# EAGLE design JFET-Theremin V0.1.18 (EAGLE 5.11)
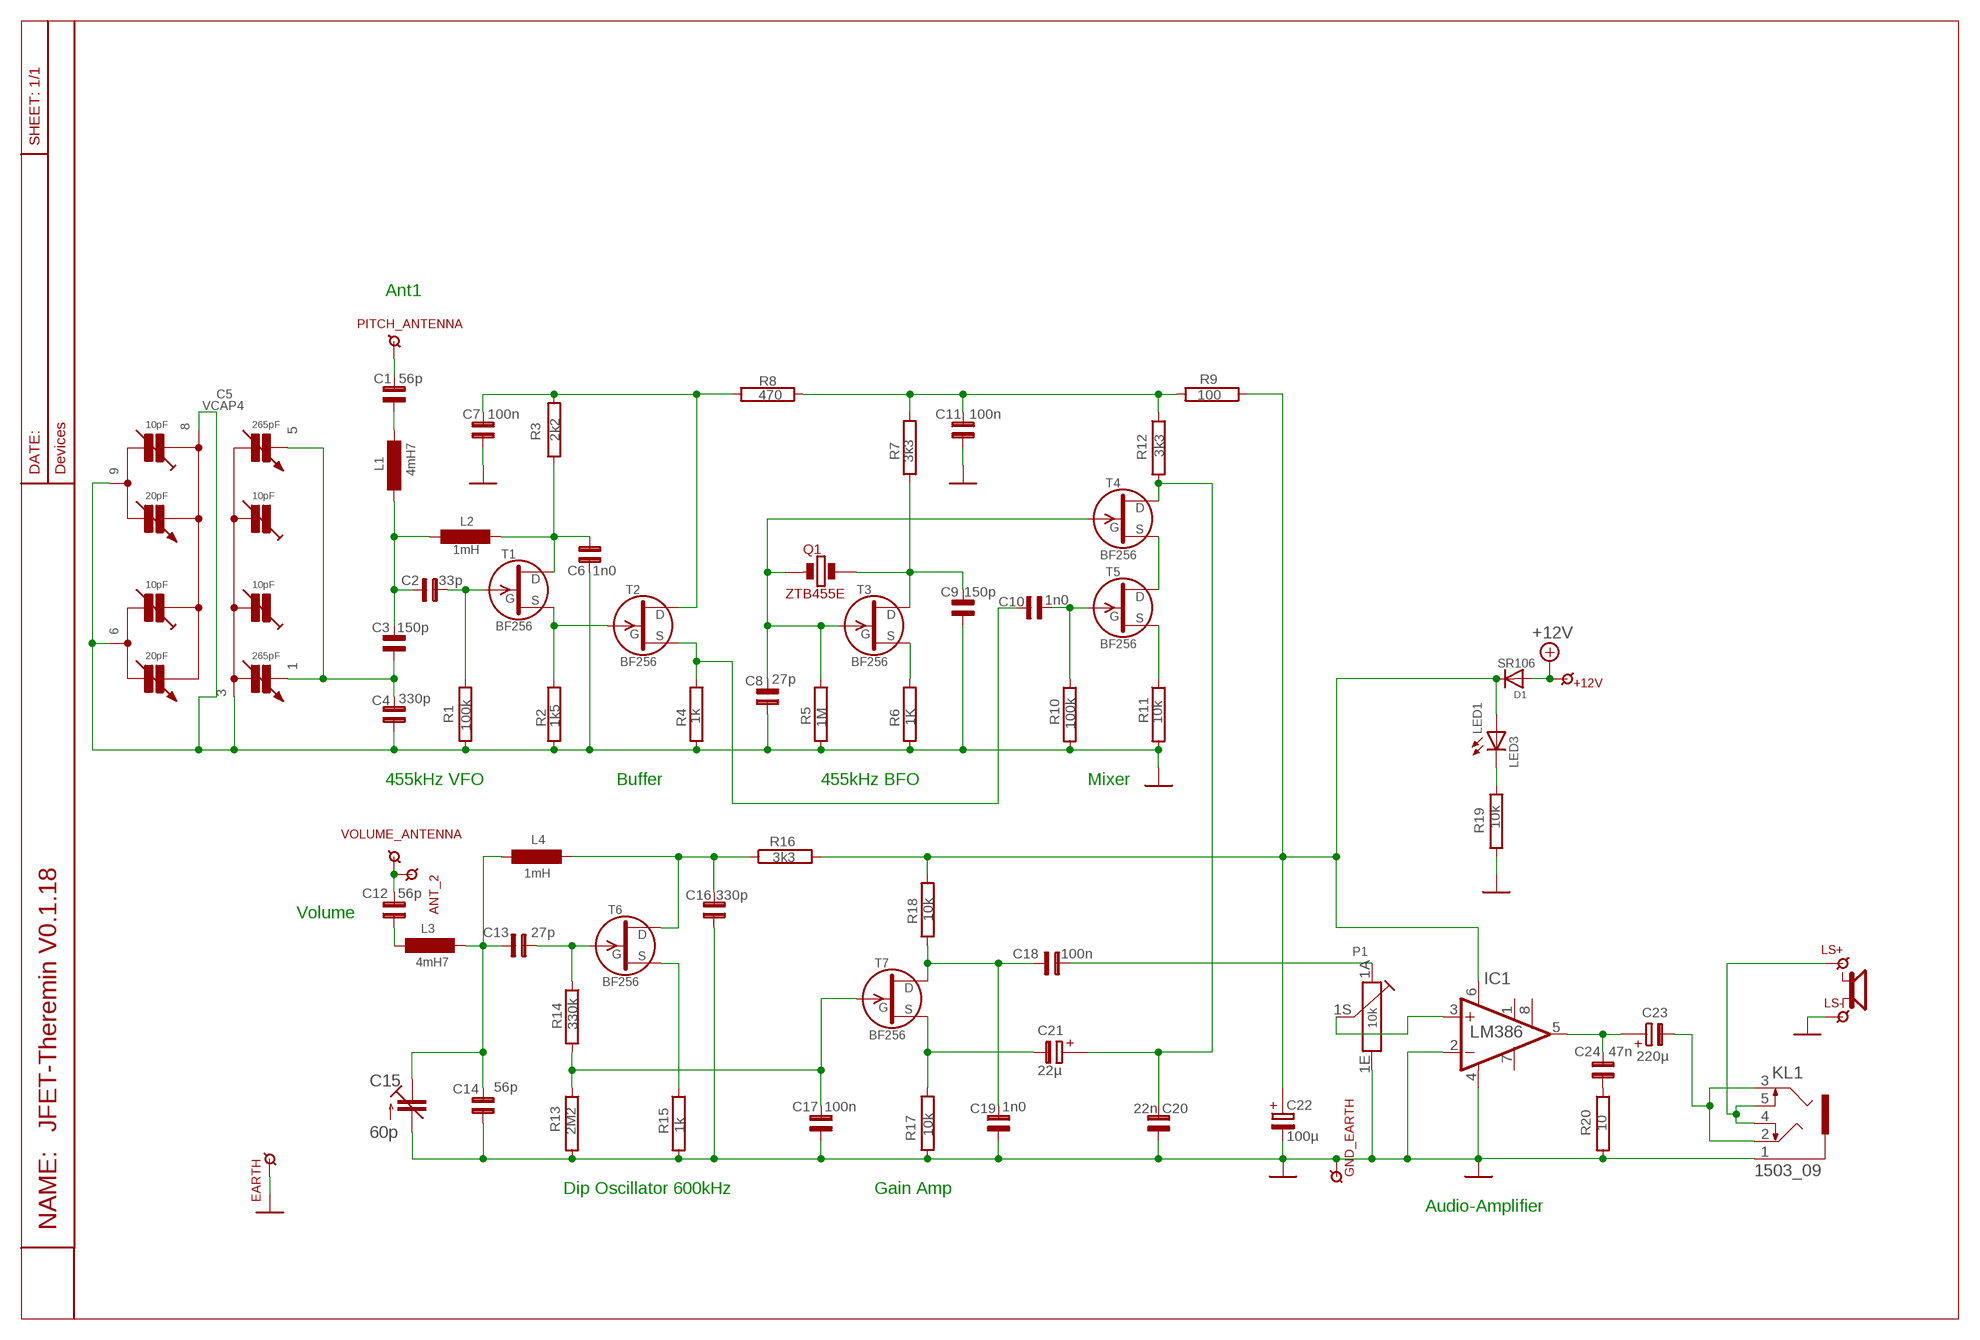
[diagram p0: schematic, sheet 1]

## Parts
+12V  AP1_GP13  [PUNKT13]
ANT_2  AP1_GP13  [PUNKT13]
C1  56p  C5B2,5E  [C5B2,5A]
C2  33p  C5B2,5E  [C5B2,5A]
C3  150p  C5B2,5E  [C5B2,5A]
C4  330p  C5B2,5E  [C5B2,5A]
C5  VCAP4  VCAP4-  [VCAP4_O]
C6  1n0  C5B2,5  [C5B2,5]
C7  100n  C5E  [C5B3,5E]
C8  27p  C5B2,5E  [C5B2,5A]
C9  150p  C5B2,5E  [C5B2,5A]
C10  1n0  C5B2,5E  [C5B2,5A]
C11  100n  C5B2,5E  [C5B2,5A]
C12  56p  C5B2,5E  [C5B2,5A]
C13  27p  C5B2,5E  [C5B2,5A]
C14  56p  C5B2,5E  [C5B2,5A]
C15  60p  C-TRIMMTZ03  [CTRIMTZ03]
C16  330p  C5B2,5E  [C5B2,5A]
C17  100n  C5B2,5E  [C5B2,5A]
C18  100n  C5B2,5E  [C5B2,5A]
C19  1n0  C5B2,5E  [C5B2,5A]
C20  22n  C5B2,5E  [C5B2,5A]
C21  22µ  E2-5  [E2-5]
C22  100µ  E2,5-6E  [E2,5-6E]
C23  220µ  E3,5-8  [E3,5-8]
C24  47n  C5B2,5  [C5B2,5]
D1  SR106  1N400410  [DO41-10]
EARTH  AP1_GP13  [PUNKT13]
GND_EARTH  AP1_GP13  [PUNKT13]
IC1  LM386  LM386N-1  [DIL08]
KL1  1503_09  [1503_09]
L1  4mH7  L-EU0207/15  [0207/15]
L2  1mH  L-EU0207/15  [0207/15]
L3  4mH7  L-EU0207/15  [0207/15]
L4  1mH  L-EU0207/15  [0207/15]
LED1  LED3  LED3MM  [LED3MM]
LS+  AP1_GP13  [PUNKT13]
LS-  AP1_GP13  [PUNKT13]
P1  10k  POTI6MM  [POTI6MM]
PITCH_ANTENNA  ANT  [ANT]
Q1  ZTB455E  ZTB_55E  [ZTB455E]
R1  100k  0207/10RD  [0207/10]
R2  1k5  0207/10RD  [0207/10]
R3  2k2  0207/10RD  [0207/10]
R4  1k  0207/10RD  [0207/10]
R5  1M  0207/10RD  [0207/10]
R6  1K  0207/10RD  [0207/10]
R7  3k3  0207/10RD  [0207/10]
R8  470  0207/10RD  [0207/10]
R9  100  0207/10RD  [0207/10]
R10  100k  0207/10RD  [0207/10]
R11  10k  0207/10RD  [0207/10]
R12  3k3  0207/10RD  [0207/10]
R13  2M2  0207/10RD  [0207/10]
R14  330k  0207/10RD  [0207/10]
R15  1k  0207/10RD  [0207/10]
R16  3k3  0207/10RD  [0207/10]
R17  10k  0207/10RD  [0207/10]
R18  10k  0207/10RD  [0207/10]
R19  10k  0207/10RD  [0207/10]
R20  10  0207/10RD  [0207/10]
T1  BF256  [TO92]
T2  BF256  [TO92]
T3  BF256  [TO92]
T4  BF256  [TO92]
T5  BF256  [TO92]
T6  BF256  [TO92]
T7  BF256  [TO92]
VOLUME_ANTENNA  AP1_GP13  [PUNKT13]

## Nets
12V: C22.+ D1.C IC1.6(VS) LED1.A R9.1 R16.2 R18.2
+12V: +12V.1 D1.A
GND: C4.1 C5.3 C5.6 C5.8 C5.9 C6.1 C7.1 C8.1 C9.1 C11.2 C14.2 C15.2(A) C16.1 C17.1 C19.2 C20.2 C22.- EARTH.1 GND_EARTH.1 IC1.2(-IN) IC1.4(GND) KL1.1 LS-.1 P1.1E R1.1 R2.1 R4.1 R5.1 R6.1 R10.2 R11.2 R13.2 R15.2 R17.1 R19.2 R20.2
N$1: C1.1 L1.1
N$2: C2.2 C3.2 L1.2 L2.1
N$3: C6.2 L2.2 R3.1 T1.3(D)
N$4: C2.1 R1.2 T1.1(G)
N$5: C7.2 R3.2 R8.2 T2.3(D)
N$6: R2.2 T1.2(S) T2.1(G)
N$7: C10.2 R4.2 T2.2(S)
N$8: C11.1 R7.2 R8.1 R9.2 R12.1
N$9: C3.1 C4.2 C5.1 C5.5
N$10: C12.1 L3.1
N$11: C9.2 Q1.P$2 R7.1 T3.3(D)
N$12: R6.2 T3.2(S)
N$13: C8.2 Q1.P$1 R5.2 T3.1(G) T4.1(G)
N$14: C13.2 C14.1 C15.1(E) L3.2 L4.1
N$15: C20.1 C21.+ R12.2 T4.3(D)
N$16: T4.2(S) T5.3(D)
N$17: C13.1 R14.1 T6.1(G)
N$18: R11.1 T5.2(S)
N$19: C10.1 R10.1 T5.1(G)
N$21: C17.2 R13.1 R14.2 T7.1(G)
N$22: C18.1 P1.1A
N$23: C23.+ C24.1 IC1.5(OUT)
N$24: R15.1 T6.2(S)
N$25: C16.2 L4.2 R16.1 T6.3(D)
N$26: ANT_2.1 C12.2 VOLUME_ANTENNA.1
N$27: C1.2 PITCH_ANTENNA.P$1
N$28: C23.- KL1.2 KL1.3
N$29: C18.2 C19.1 R18.1 T7.3(D)
N$30: C21.- R17.2 T7.2(S)
N$31: IC1.3(+IN) P1.1S
N$32: C24.2 R20.1
N$33: KL1.4 KL1.5 LS+.1
N$35: LED1.K(C) R19.1
Unconnected: IC1.1(GAIN) IC1.7(BYPASS) IC1.8(GAIN)

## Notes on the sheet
- Ant1
- 455kHz VFO | Buffer | 455kHz BFO | Mixer
- Volume
- Dip Oscillator 600kHz | Gain Amp
- Audio-Amplifier

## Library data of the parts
+12V ANT_2 EARTH GND_EARTH LS+ LS- VOLUME_ANTENNA = VERBINDE:AP1_G
C1-C4 C8-C14 C16-C20 = CAP-Kondensatoren:C5B2,5E
C5 = MB-VCaps:VCAP4
C6 C24 = CAP-Kondensatoren:C5B2,5
C7 = CAP-Kondensatoren:C5E
C15 = resistor:C-TRIMM: Trimm capacitor
C21 = Elkos:E2-5
C22 = Elkos:E2,5-6E
C23 = Elkos:E3,5-8
D1 = diode:1N4004: DIODE
IC1 = linear:LM386?-*: Low Voltage Audio Power Amplifier Source: http://cache.national.com/ds/LM/LM386.pdf
KL1 = con-lumberg:1503_09: Jack connectors according to JISC 6560, 3.5 mm Klinkeneinbaukupplung nach JISC 6560, 3,5 mm, 3-polig/ stereo, abgewinkelte Ausführung, mit 2 Öffnern und Lötaugen, für Leiterplatten Rückseitenmontage Source: http://www.lumberg.com/Produkte/PDFs/1503_09.pdf
L1-L4 = rcl:L-EU: INDUCTOR, European symbol
LED1 = LED´s:LED: LED
P1 = Potentiometer-piher:POTI6MM
PITCH_ANTENNA = VERBINDE:ANT
Q1 = ZTB455E:ZTB_55E
R1-R20 = R:0207/10
T1-T7 = transistor-fet+irf7201:BF256: N-Channel Junction FET

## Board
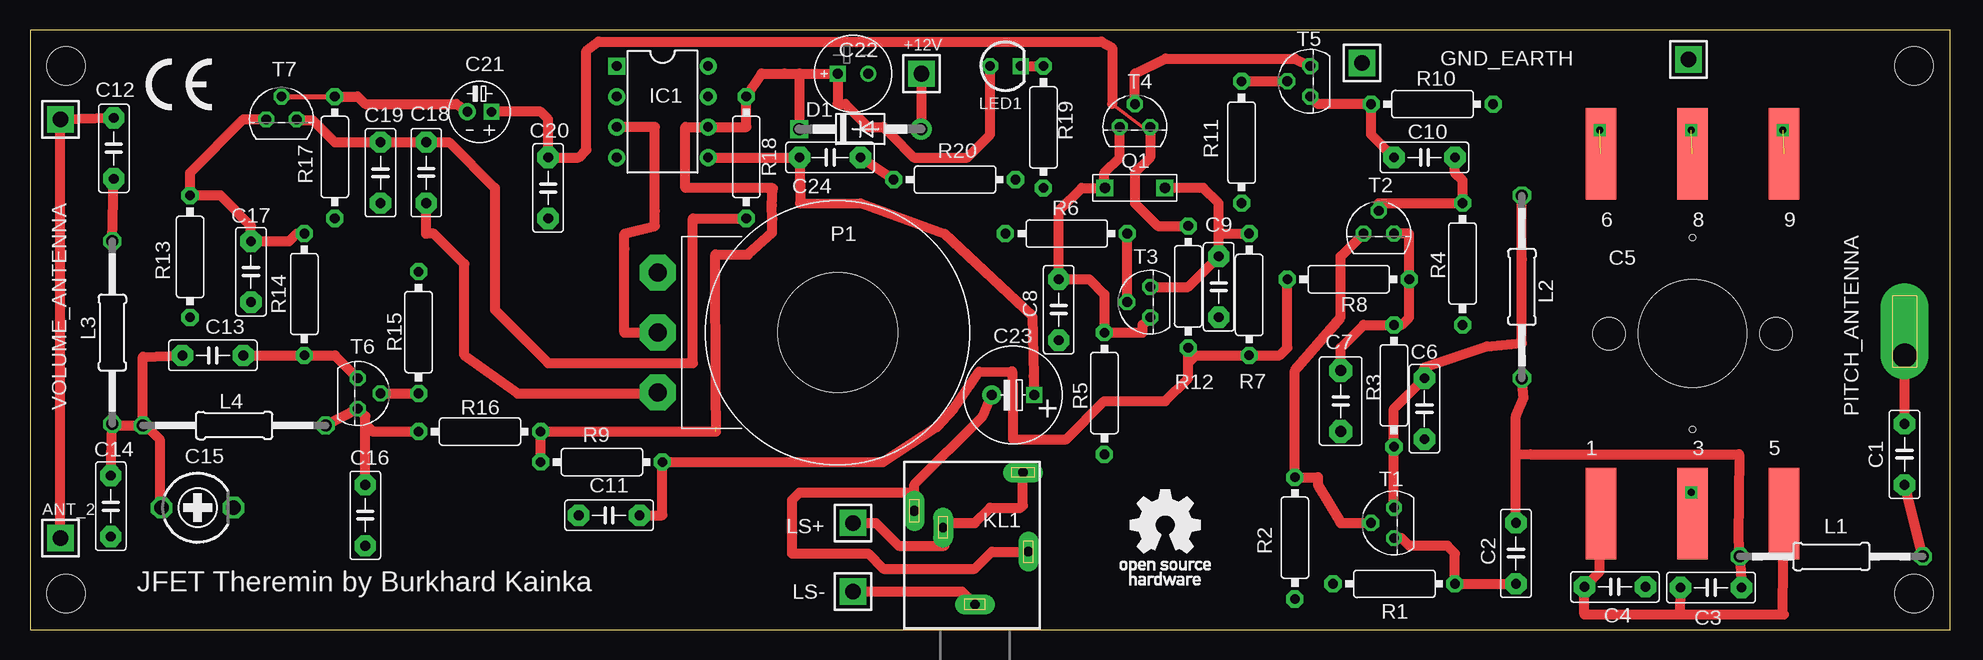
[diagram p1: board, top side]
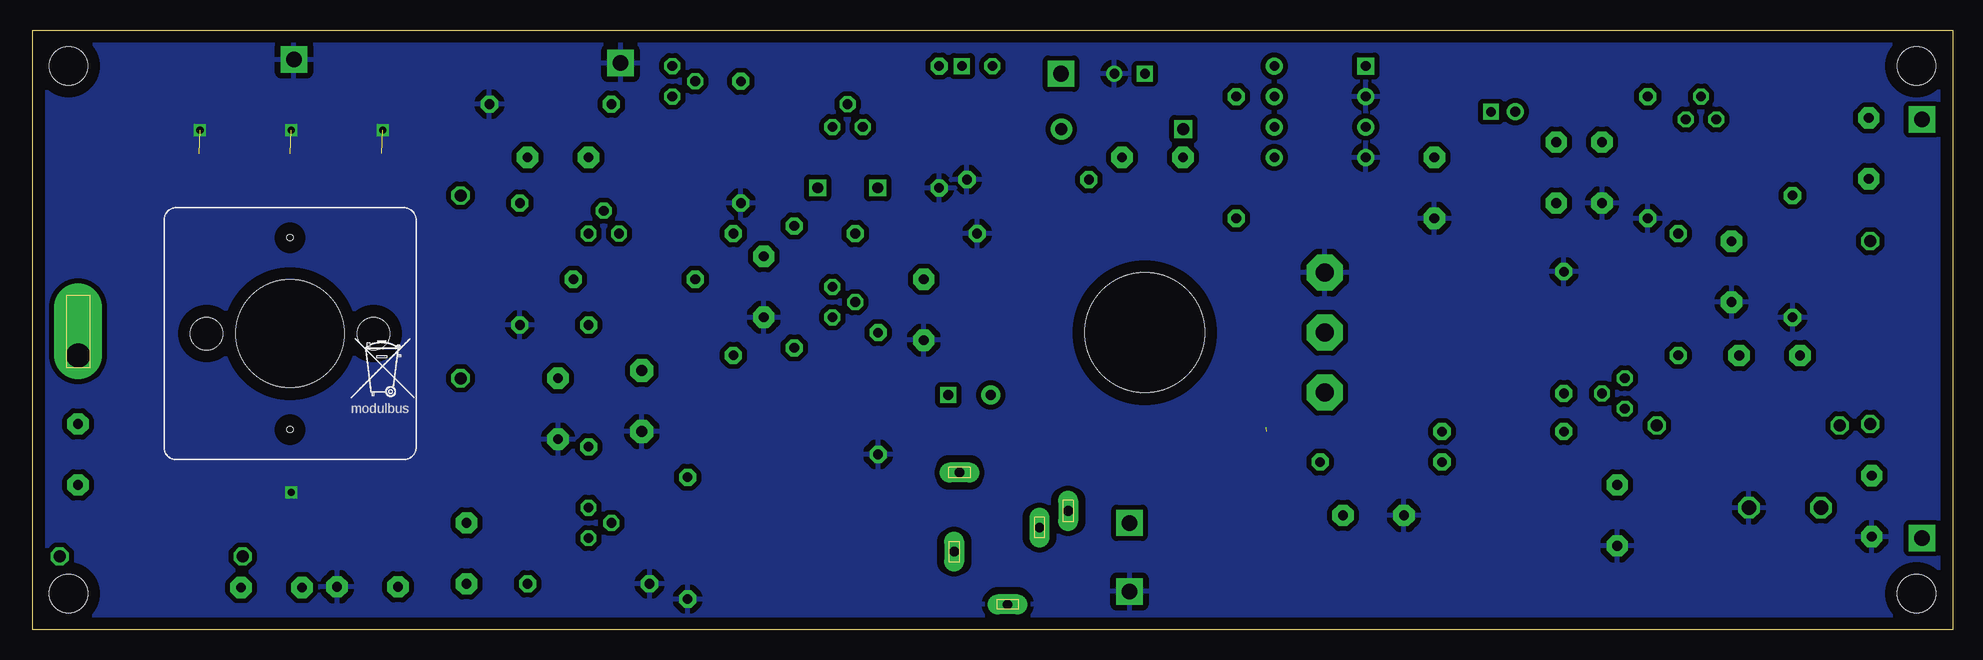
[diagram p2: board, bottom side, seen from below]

Size 160 x 50 mm. Coordinates in mm from the lower left corner, seen from the top.
Outline: 0,0 160,0 160,50 0,50 0,0
Copper layers (1*16): Top 0.035mm / dielectric 1.5mm / Bottom 0.035mm
Design rules "default": minimum track width 10mil, minimum drill 23mil, track to track 8mil, track to pad 8mil, pad to pad 8mil, via to via 8mil, smd to smd 8mil, copper to edge 40mil, drill to drill 8mil, minimum pad ring 10mil, minimum via ring 8mil, stop-mask expansion 4mil, vias tented up to drill 0mil, thermal gap 20mil
Holes 3.2 mm at 157,47 157,3 3,3 3,47

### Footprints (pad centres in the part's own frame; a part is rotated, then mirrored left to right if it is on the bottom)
PUNKT13 = drill 1.3 pad 2.184 square: 1 0,0
C5B2,5A = drill 0.813 pad 1.778 octagon: 1 -2.54,0; 2 2.54,0
VCAP4_O = smd 2.54 x 7.62: 1 -7.62,-15; 3 0,-15; 5 7.62,-15; 6 -7.62,15; 8 0,15; 9 7.62,15 | hole 9: 0,0 | hole 2.7: -6.95,0; 6.95,0 | hole 0.5: 0,-8; 0,8
C5B2,5 = drill 0.813 pad 1.778 octagon: 1 -2.54,0; 2 2.54,0
C5B3,5E = drill 0.914 pad 1.905 octagon: 1 -2.54,0; 2 2.54,0
CTRIMTZ03 = drill 1.2 octagon: 1 0,3; 2 0,-3
E2-5 = drill 0.8 square: + -1,0 | drill 0.813 pad 1.422 round: - 1.016,0
E2,5-6E = drill 0.8 square: + 0,0 | drill 0.8 round: - 2.54,0
E3,5-8 = drill 0.813 square: + -1.778,0 | drill 0.813 pad 1.6 round: - 1.778,0
DO41-10 = drill 1 pad 1.778 round: A 5.08,0 | drill 1 square: C -5.08,0
DIL08 = drill 0.8 pad 1.422 square: 1 -3.81,-3.81 | drill 0.8 pad 1.422 round: 2 -1.27,-3.81; 3 1.27,-3.81; 4 3.81,-3.81; 5 3.81,3.81; 6 1.27,3.81; 7 -1.27,3.81; 8 -3.81,3.81
1503_09 = drill 0.8 pad 1.676 long: 1 0,-2.1; 2 -4.45,-6.5; 3 5.05,-9.9; 4 -4,-13.1; 5 2.65,-8.5
0207/15 = drill 1 octagon: 1 -7.62,0; 2 7.62,0
LED3MM = drill 0.813 octagon: A -1.27,0 | drill 0.813 square: K 1.27,0
POTI6MM = drill 1.5 pad 3 octagon: 1A 15,5; 1E 15,-5; 1S 15,0 | hole 10: 0,0
ANT = drill 2 pad 4 offset: P$1 0,0
ZTB455E = drill 0.9 square: P$1 2.5,0; P$2 -2.5,0
0207/10 = drill 0.8 pad 1.422 octagon: 1 -5.08,0; 2 5.08,0
TO92 = drill 0.813 octagon: 1 -1.27,0; 2 0,1.905; 3 1.27,0

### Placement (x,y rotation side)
+12V  74.3,46.35 0 top
ANT_2  2.54,7.62 0 top
C1  156.21,14.61 90 top
C2  123.83,6.35 90 top
C3  140.09,3.5 0 top
C4  132.08,3.56 180 top
C5  138.54,24.68 0 top
C6  116.2,18.41 90 top
C7  109.22,19.05 90 top
C8  85.72,26.67 90 top
C9  99.06,28.57 90 top
C10  116.2,39.37 0 top
C11  48.26,9.53 180 top
C12  6.99,40.13 90 top
C13  15.24,22.86 180 top
C14  6.73,10.29 270 top
C15  13.97,10.16 90 top
C16  27.94,9.53 90 top
C17  18.41,29.84 90 top
C18  33.02,38.1 90 top
C19  29.21,38.1 270 top
C20  43.18,36.83 270 top
C21  37.47,43.18 180 top
C22  67.31,46.35 0 top
C23  81.92,19.56 180 top
C24  66.67,39.37 0 top
D1  69.18,41.73 0 top
EARTH  111,47.24 0 top
GND_EARTH  138.21,47.53 0 top
IC1  52.7,43.18 270 top
KL1  78.74,0 180 top
L1  150.11,6.1 180 top
L2  124.33,28.57 90 top
L3  6.86,24.77 270 top
L4  17.02,17.02 0 top
LED1  81.28,46.99 0 top
LS+  68.58,8.89 90 top
LS-  68.58,3.17 90 top
P1  67.31,24.77 180 top
PITCH_ANTENNA  156.21,22.86 90 top
Q1  92.08,36.83 180 top
R1  113.67,3.81 0 top
R2  105.41,7.62 90 top
R3  113.67,20.32 90 top
R4  119.38,30.48 90 top
R5  89.53,19.68 90 top
R6  86.36,33.02 0 top
R7  101.6,27.94 270 top
R8  109.86,29.21 0 top
R9  47.62,13.97 0 top
R10  116.84,43.81 0 top
R11  100.97,40.64 270 top
R12  96.52,28.57 90 top
R13  13.34,31.11 270 top
R14  22.86,27.94 90 top
R15  32.38,24.77 90 top
R16  37.47,16.51 0 top
R17  25.4,39.37 90 top
R18  59.69,39.37 90 top
R19  84.45,41.91 270 top
R20  77.05,37.52 0 top
T1  113.67,8.89 90 top
T2  112.39,33.02 0 top
T3  93.34,27.3 90 top
T4  92.08,41.91 0 top
T5  106.68,45.72 90 top
T6  27.3,19.68 270 top
T7  20.95,42.55 0 top
U$10  [OSH8MM]  90.81,3.68 0 top
U$11  [CE6MM]  9.65,43.31 0 top
U$12  [MÜLL8]  133.48,19.3 0 bottom
VOLUME_ANTENNA  2.54,42.55 90 top

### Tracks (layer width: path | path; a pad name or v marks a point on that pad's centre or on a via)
12V  (1 unrouted)
  Top 0.813: R9.1 R16.2 57.15,16.51 | 64.14,46.35 62.87,46.35 60.96,46.35 R18.2 59.69,41.91 IC1.6 54.61,41.91 54.61,36.83 61.9,36.8 61.82,35.37 61.86,34.24 61.85,33.1 59.82,31.26 57.12,31.29 57.15,19.68 57.18,16.87 | 64.14,46.35 C22.+ 67.31,43.81 67.94,43.81 69.85,41.91 71.12,41.91 71.75,41.27 73.66,39.37 78.11,39.37 80.01,41.27 LED1.A | D1.C 64.1,46.32 64.14,46.35
+12V
  Top 0.813: +12V.1 74.3,41.77 D1.A
GND  (via drill 0.6)  (3 unrouted)
  Top 0.813: LS-.1 77.67,3.17 KL1.1 | C5.3 v138.43,11.43
  other vias: 130.81,41.66 138.43,41.66 146.05,41.66
  pour Bottom (isolate 0.406): 0,0 160.02,0 160.02,50.16 0,50.16
N$1
  Top 0.813: L1.1 C1.1
N$2
  Top 0.813: L2.1 124.46,19.3 123.83,17.78 123.83,14.63 | C3.2 L1.2 142.37,7.49 142.43,14.62 125.03,14.62 123.83,14.63 | C2.2 123.83,14.63
N$3
  Top 0.813: L2.2 124.33,30.86 124.33,23.88 121.41,23.62 116.2,21.84 C6.2 113.67,18.41 R3.1 T1.3
N$4
  Top 0.813: C2.1 R1.2 118.75,6.35 118.11,6.99 114.94,6.99 114.3,7.62 T1.1
N$5
  Top 0.813: T2.3 114.94,33.02 R8.2 114.94,26.04 114.3,25.4 R3.2 111.12,25.4 109.22,23.5 C7.2
N$6
  Top 0.813: T1.2 109.22,8.89 107.31,12.06 107.31,12.7 R2.2 105.41,21.59 109.22,26.04 109.22,31.11 T2.1
N$7
  Top 0.813: C10.2 118.75,38.1 119.38,37.47 R4.2 112.39,35.56 T2.2
N$8
  Top 0.813: C11.1 52.7,9.53 R9.2 71.09,13.97 75.56,16.89 76.96,18.44 79.08,21.49 81.85,21.54 81.92,19.68 81.92,15.88 86.36,15.88 89.53,19.05 94.61,19.05 96.52,20.95 96.52,22.23 | 96.52,22.23 R12.1 | 96.52,22.23 97.16,22.86 R7.2 104.14,22.86 104.78,23.5 R8.1
N$9
  Top 0.813: 137.54,1.27 129.54,1.27 C4.2 130.81,4.83 130.81,6.99 130.81,11.43 C5.1 | 137.54,1.27 C3.1 | 137.54,1.27 146.18,1.27 146.05,1.4 C5.5
N$10
  Top 0.813: L3.1 C12.1
N$11
  Top 0.813: T3.3 96.52,28.57 C9.2 99.06,33.02 | Q1.P$2 97.79,36.83 99.06,35.56 99.06,33.02 | 99.06,33.02 R7.1
N$12
  Top 0.813: T3.2 R6.2
N$13
  Top 0.813: T4.1 90.81,39.37 89.53,38.1 89.53,36.87 Q1.P$1 87.63,36.83 85.72,34.92 C8.2 88.27,29.21 89.53,27.94 R5.2 92.71,24.77 92.71,25.4 T3.1
N$14
  Top 0.813: C14.1 L3.2 6.99,17.02 L4.1 | L4.1 10.16,16.51 10.79,15.88 10.79,10.34 C15.1 | L4.1 9.4,22.73 C13.2
N$15
  Top 0.305: 90.17,43.81 92.71,41.91 T4.3
  Top 0.813: C21.+ 42.55,43.18 43.18,42.55 C20.1 45.72,39.37 46.35,40.01 46.35,48.26 47.37,49.02 89.28,49.02 90.17,48.51 90.17,43.81 | T4.3 93.34,39.37 92.08,38.1 92.08,35.56 93.98,33.66 R12.2
N$16
  Top 0.813: T4.2 92.08,46.35 94.61,47.62 105.41,47.62 T5.3
N$17
  Top 0.813: C13.1 R14.1 25.4,22.86 T6.1
N$18
  Top 0.813: R11.1 T5.2
N$19
  Top 0.813: C10.1 111.76,41.27 R10.1 107.31,43.81 T5.1
N$21
  Top 0.813: R14.2 22.23,33.02 21.59,32.38 C17.2 18.41,33.66 15.88,36.2 R13.1 13.34,38.1 17.78,42.55 T7.1
N$22
  Top 0.813: C18.1 33.02,33.02 33.66,33.02 36.2,30.48 36.2,22.86 40.64,19.68 52.23,19.68 P1.1A
N$23
  Top 0.813: IC1.5 C24.1 64.17,35.54 69.22,35.56 76.2,33.02 83.51,26.13 83.64,21.14 83.66,20.48 C23.+
N$24
  Top 0.813: T6.2 R15.1
N$25
  Top 0.813: L4.2 T6.3 27.94,17.78 27.94,17.14 | C16.2 27.94,17.14 | 27.94,17.14 28.57,16.51 R16.1
N$26
  Top 0.813: ANT_2.1 VOLUME_ANTENNA.1 C12.2
N$27
  Top 0.813: C1.2 PITCH_ANTENNA.P$1
N$28
  Top 0.813: 73.69,11.43 KL1.3 | 73.69,11.43 73.69,12.1 79.38,17.78 C23.- | KL1.2 80.16,6.5 78.74,5.08 71.12,5.08 69.85,6.35 63.5,6.35 63.5,10.79 64.14,11.43 73.69,11.43
N$29
  Top 0.813: T7.3 22.26,42.55 22.33,42.48 23.56,42.48 25.4,40.64 C19.1 C18.2 34.92,40.64 38.73,36.83 38.73,26.67 43.18,22.23 44.45,22.23 55.24,22.23 55.24,34.29 R18.1
N$30
  Top 0.406: T7.2 R17.2
  Top 0.813: R17.2 27.3,44.45 27.94,43.81 35.56,43.81 C21.-
N$31
  Top 0.813: IC1.3 52.07,41.91 52.07,34.92 52.07,33.66 49.53,33.02 49.53,31.75 49.53,24.77 P1.1S
N$32
  Top 0.813: R20.1 C24.2
N$33
  Top 0.813: LS+.1 70.48,8.89 72.39,6.99 76.2,6.99 76.2,8.39 KL1.5 76.48,8.89 78.74,8.89 80.01,10.16 82.55,10.16 82.74,10.35 KL1.4
N$35
  Top 0.813: LED1.K R19.1

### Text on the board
tNames: JFET Theremin by Burkhard Kainka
